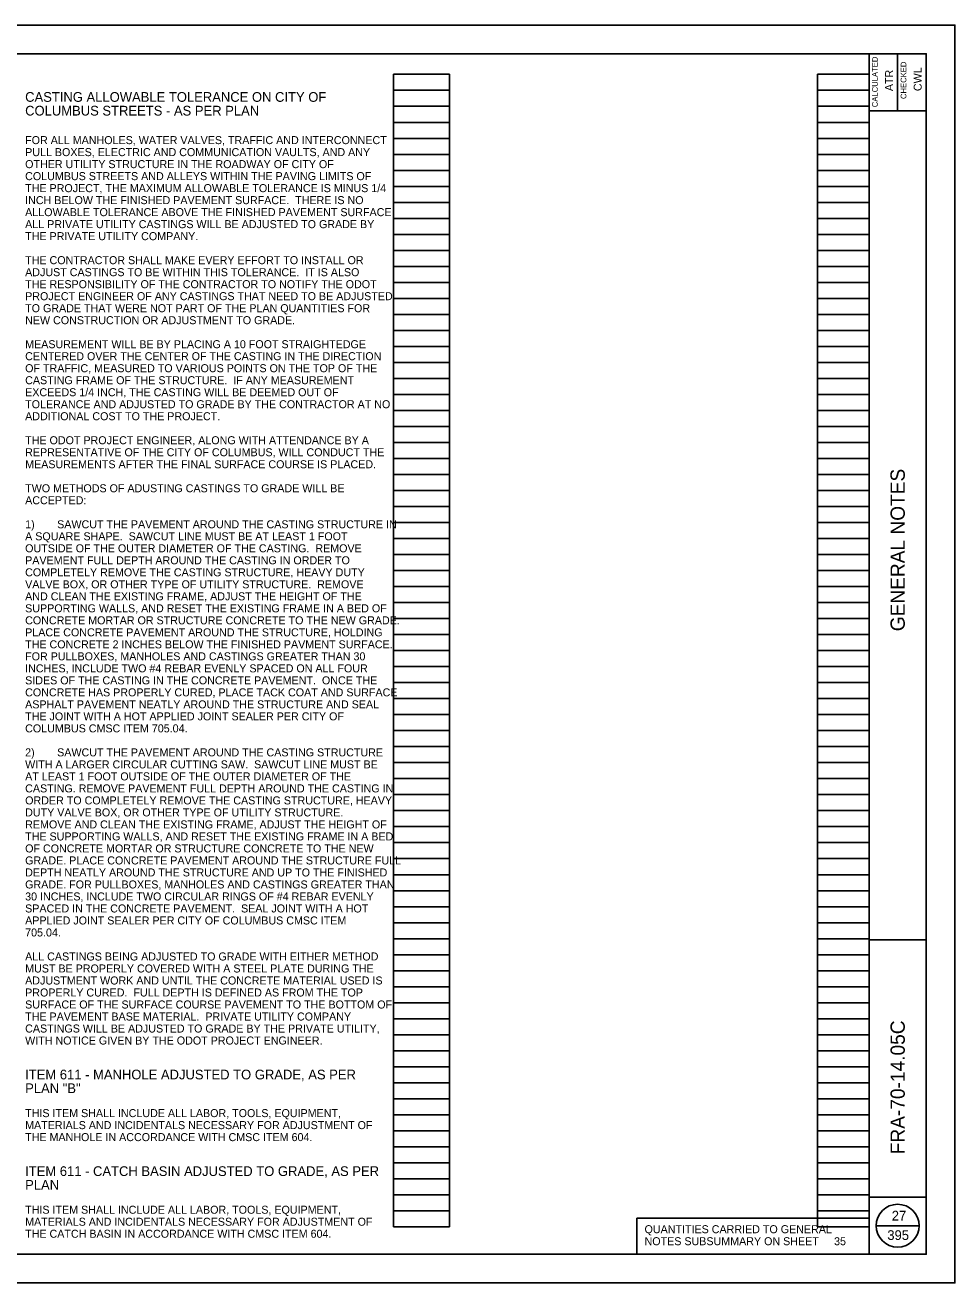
# Model space of a CAD drawing. Extents: x 0 to 34, y 0 to 22.
# Drawn here: x 17.74 to 34, y 0 to 22 of the extents above; entities that cross this region are included whole.
import ezdxf

# ---------------------------------------------------------------- set-up
doc = ezdxf.new("R2010")
doc.units = 0
for name, color, linetype in [('SC_Scratch1', 7, 'Continuous'), ('SH_Border', 7, 'Continuous'), ('SH_Cut_Line', 7, 'Continuous'), ('SH_Data', 7, 'Continuous'), ('SH_Text', 7, 'Continuous'), ('TX_P_1', 7, 'Continuous'), ('TX_P_Misc', 7, 'Continuous')]:
    doc.layers.add(name, color=color, linetype=linetype)

msp = doc.modelspace()

# ---------------------------------------------------------------- linework, layer by layer
at = {"layer": 'SC_Scratch1'}
for p, q in [((24.18, 0.98), (24.18, 21.14)), ((24.18, 21.14), (25.16, 21.14)), ((25.16, 0.98), (25.16, 21.14)), ((31.6, 0.98), (31.6, 21.14)), ((31.6, 21.14), (32.5, 21.14)), ((32.5, 0.98), (32.5, 21.14)), ((24.18, 20.86), (25.16, 20.86)), ((31.6, 20.86), (32.5, 20.86)), ((24.18, 20.58), (25.16, 20.58)), ((31.6, 20.58), (32.5, 20.58)), ((24.18, 20.3), (25.16, 20.3)), ((31.6, 20.3), (32.5, 20.3)), ((24.18, 20.02), (25.16, 20.02)), ((31.6, 20.02), (32.5, 20.02)), ((24.18, 19.74), (25.16, 19.74)), ((31.6, 19.74), (32.5, 19.74)), ((24.18, 19.46), (25.16, 19.46)), ((31.6, 19.46), (32.5, 19.46)), ((24.18, 19.18), (25.16, 19.18)), ((31.6, 19.18), (32.5, 19.18)), ((24.18, 18.9), (25.16, 18.9)), ((31.6, 18.9), (32.5, 18.9)), ((24.18, 18.62), (25.16, 18.62)), ((31.6, 18.62), (32.5, 18.62)), ((24.18, 18.34), (25.16, 18.34)), ((31.6, 18.34), (32.5, 18.34)), ((24.18, 18.06), (25.16, 18.06)), ((31.6, 18.06), (32.5, 18.06)), ((24.18, 17.78), (25.16, 17.78)), ((31.6, 17.78), (32.5, 17.78)), ((24.18, 17.5), (25.16, 17.5)), ((31.6, 17.5), (32.5, 17.5)), ((24.18, 17.22), (25.16, 17.22)), ((31.6, 17.22), (32.5, 17.22)), ((24.18, 16.94), (25.16, 16.94)), ((31.6, 16.94), (32.5, 16.94)), ((24.18, 16.66), (25.16, 16.66)), ((31.6, 16.66), (32.5, 16.66)), ((24.18, 16.38), (25.16, 16.38)), ((31.6, 16.38), (32.5, 16.38)), ((24.18, 16.1), (25.16, 16.1)), ((31.6, 16.1), (32.5, 16.1)), ((24.18, 15.82), (25.16, 15.82)), ((31.6, 15.82), (32.5, 15.82)), ((24.18, 15.54), (25.16, 15.54)), ((31.6, 15.54), (32.5, 15.54)), ((24.18, 15.26), (25.16, 15.26)), ((31.6, 15.26), (32.5, 15.26)), ((24.18, 14.98), (25.16, 14.98)), ((31.6, 14.98), (32.5, 14.98)), ((24.18, 14.7), (25.16, 14.7)), ((31.6, 14.7), (32.5, 14.7)), ((24.18, 14.42), (25.16, 14.42)), ((31.6, 14.42), (32.5, 14.42)), ((24.18, 14.14), (25.16, 14.14)), ((31.6, 14.14), (32.5, 14.14)), ((24.18, 13.86), (25.16, 13.86)), ((31.6, 13.86), (32.5, 13.86)), ((24.18, 13.58), (25.16, 13.58)), ((31.6, 13.58), (32.5, 13.58)), ((24.18, 13.3), (25.16, 13.3)), ((31.6, 13.3), (32.5, 13.3)), ((24.18, 13.02), (25.16, 13.02)), ((31.6, 13.02), (32.5, 13.02)), ((24.18, 12.74), (25.16, 12.74)), ((31.6, 12.74), (32.5, 12.74)), ((24.18, 12.46), (25.16, 12.46)), ((31.6, 12.46), (32.5, 12.46)), ((24.18, 12.18), (25.16, 12.18)), ((31.6, 12.18), (32.5, 12.18)), ((24.18, 11.9), (25.16, 11.9)), ((31.6, 11.9), (32.5, 11.9)), ((24.18, 11.62), (25.16, 11.62)), ((31.6, 11.62), (32.5, 11.62)), ((24.18, 11.34), (25.16, 11.34)), ((31.6, 11.34), (32.5, 11.34)), ((24.18, 11.06), (25.16, 11.06)), ((31.6, 11.06), (32.5, 11.06)), ((24.18, 10.78), (25.16, 10.78)), ((31.6, 10.78), (32.5, 10.78)), ((24.18, 10.5), (25.16, 10.5)), ((31.6, 10.5), (32.5, 10.5)), ((24.18, 10.22), (25.16, 10.22)), ((31.6, 10.22), (32.5, 10.22)), ((24.18, 9.94), (25.16, 9.94)), ((31.6, 9.94), (32.5, 9.94)), ((24.18, 9.66), (25.16, 9.66)), ((31.6, 9.66), (32.5, 9.66)), ((24.18, 9.38), (25.16, 9.38)), ((31.6, 9.38), (32.5, 9.38)), ((24.18, 9.1), (25.16, 9.1)), ((31.6, 9.1), (32.5, 9.1)), ((24.18, 8.82), (25.16, 8.82)), ((31.6, 8.82), (32.5, 8.82)), ((24.18, 8.54), (25.16, 8.54)), ((31.6, 8.54), (32.5, 8.54)), ((24.18, 8.26), (25.16, 8.26)), ((31.6, 8.26), (32.5, 8.26)), ((24.18, 7.98), (25.16, 7.98)), ((31.6, 7.98), (32.5, 7.98)), ((24.18, 7.7), (25.16, 7.7)), ((31.6, 7.7), (32.5, 7.7)), ((24.18, 7.42), (25.16, 7.42)), ((31.6, 7.42), (32.5, 7.42)), ((24.18, 7.14), (25.16, 7.14)), ((31.6, 7.14), (32.5, 7.14)), ((24.18, 6.86), (25.16, 6.86)), ((31.6, 6.86), (32.5, 6.86)), ((24.18, 6.58), (25.16, 6.58)), ((31.6, 6.58), (32.5, 6.58)), ((24.18, 6.3), (25.16, 6.3)), ((31.6, 6.3), (32.5, 6.3)), ((24.18, 6.02), (25.16, 6.02)), ((31.6, 6.02), (32.5, 6.02)), ((24.18, 5.74), (25.16, 5.74)), ((31.6, 5.74), (32.5, 5.74)), ((24.18, 5.46), (25.16, 5.46)), ((31.6, 5.46), (32.5, 5.46)), ((24.18, 5.18), (25.16, 5.18)), ((31.6, 5.18), (32.5, 5.18)), ((24.18, 4.9), (25.16, 4.9)), ((31.6, 4.9), (32.5, 4.9)), ((24.18, 4.62), (25.16, 4.62)), ((31.6, 4.62), (32.5, 4.62)), ((24.18, 4.34), (25.16, 4.34)), ((31.6, 4.34), (32.5, 4.34)), ((24.18, 4.06), (25.16, 4.06)), ((31.6, 4.06), (32.5, 4.06)), ((24.18, 3.78), (25.16, 3.78)), ((31.6, 3.78), (32.5, 3.78)), ((24.18, 3.5), (25.16, 3.5)), ((31.6, 3.5), (32.5, 3.5)), ((24.18, 3.22), (25.16, 3.22)), ((31.6, 3.22), (32.5, 3.22)), ((24.18, 2.94), (25.16, 2.94)), ((31.6, 2.94), (32.5, 2.94)), ((24.18, 2.66), (25.16, 2.66)), ((31.6, 2.66), (32.5, 2.66)), ((24.18, 2.38), (25.16, 2.38)), ((31.6, 2.38), (32.5, 2.38)), ((24.18, 2.1), (25.16, 2.1)), ((31.6, 2.1), (32.5, 2.1)), ((24.18, 1.82), (25.16, 1.82)), ((31.6, 1.82), (32.5, 1.82)), ((24.18, 1.54), (25.16, 1.54)), ((31.6, 1.54), (32.5, 1.54)), ((24.18, 1.26), (25.16, 1.26)), ((31.6, 1.26), (32.5, 1.26)), ((24.18, 0.98), (25.16, 0.98)), ((31.6, 0.98), (32.5, 0.98))]:
    msp.add_line(p, q, dxfattribs=at)
at = {"layer": 'SH_Border'}
for p, q in [((32.5, 0.5), (32.5, 21.5)), ((33, 21.5), (33, 20.5)), ((32.5, 20.5), (33.5, 20.5)), ((32.5, 6), (33.5, 6)), ((32.5, 1.5), (33.5, 1.5))]:
    msp.add_line(p, q, dxfattribs=at)
msp.add_lwpolyline([(2, 21.5), (33.5, 21.5), (33.5, 0.5), (2, 0.5)], close=True, dxfattribs=at)
at = {"layer": 'SH_Cut_Line'}
msp.add_lwpolyline([(0, 0), (34, 0), (34, 22), (0, 22)], close=True, dxfattribs=at)
at = {"layer": 'SH_Data'}
msp.add_line((32.625, 1), (33.375, 1), dxfattribs=at)
msp.add_circle((33, 1), 0.375, dxfattribs=at)
at = {"layer": 'TX_P_1'}
msp.add_lwpolyline([(28.437, 1.132), (32.5, 1.132), (32.5, 0.5), (28.437, 0.5)], close=True, dxfattribs=at)

# ---------------------------------------------------------------- texts
at = {"layer": 'SH_Data'}
for s, height, p in [('CALCULATED', 0.1, (32.652, 20.565)), ('CHECKED', 0.1, (33.152, 20.708)), ('ATR', 0.14, (32.92, 20.846)), ('CWL', 0.14, (33.42, 20.846)), ('GENERAL NOTES', 0.25, (33.125, 11.398)), ('FRA-70-14.05C', 0.25, (33.125, 2.249))]:
    msp.add_text(s, height=height, rotation=90, dxfattribs=at).set_placement(p)
for s, p in [('27', (32.897, 1.09)), ('395', (32.819, 0.75))]:
    msp.add_text(s, height=0.17, dxfattribs=at).set_placement(p)
at = {"layer": 'SH_Text'}
for s, p in [('FOR ALL MANHOLES, WATER VALVES, TRAFFIC AND INTERCONNECT ', (17.74, 19.919)), ('PULL BOXES, ELECTRIC AND COMMUNICATION VAULTS, AND ANY ', (17.74, 19.709)), ('OTHER UTILITY STRUCTURE IN THE ROADWAY OF CITY OF ', (17.74, 19.499)), ('COLUMBUS STREETS AND ALLEYS WITHIN THE PAVING LIMITS OF ', (17.74, 19.289)), ('THE PROJECT, THE MAXIMUM ALLOWABLE TOLERANCE IS MINUS 1/4 ', (17.74, 19.079)), ('INCH BELOW THE FINISHED PAVEMENT SURFACE.  THERE IS NO ', (17.74, 18.869)), ('ALLOWABLE TOLERANCE ABOVE THE FINISHED PAVEMENT SURFACE. ', (17.74, 18.659)), ('ALL PRIVATE UTILITY CASTINGS WILL BE ADJUSTED TO GRADE BY ', (17.74, 18.449)), ('THE PRIVATE UTILITY COMPANY.', (17.74, 18.239)), ('THE CONTRACTOR SHALL MAKE EVERY EFFORT TO INSTALL OR ', (17.74, 17.819)), ('ADJUST CASTINGS TO BE WITHIN THIS TOLERANCE.  IT IS ALSO ', (17.74, 17.609)), ('THE RESPONSIBILITY OF THE CONTRACTOR TO NOTIFY THE ODOT ', (17.74, 17.399)), ('PROJECT ENGINEER OF ANY CASTINGS THAT NEED TO BE ADJUSTED ', (17.74, 17.189)), ('TO GRADE THAT WERE NOT PART OF THE PLAN QUANTITIES FOR ', (17.74, 16.979)), ('NEW CONSTRUCTION OR ADJUSTMENT TO GRADE.', (17.74, 16.769)), ('CENTERED OVER THE CENTER OF THE CASTING IN THE DIRECTION ', (17.74, 16.139)), ('MEASUREMENT WILL BE BY PLACING A 10 FOOT STRAIGHTEDGE ', (17.74, 16.349)), ('OF TRAFFIC, MEASURED TO VARIOUS POINTS ON THE TOP OF THE ', (17.74, 15.929)), ('CASTING FRAME OF THE STRUCTURE.  IF ANY MEASUREMENT ', (17.74, 15.719)), ('EXCEEDS 1/4 INCH, THE CASTING WILL BE DEEMED OUT OF ', (17.74, 15.509)), ('TOLERANCE AND ADJUSTED TO GRADE BY THE CONTRACTOR AT NO ', (17.74, 15.299)), ('ADDITIONAL COST TO THE PROJECT.', (17.74, 15.089)), ('THE ODOT PROJECT ENGINEER, ALONG WITH ATTENDANCE BY A ', (17.74, 14.669)), ('REPRESENTATIVE OF THE CITY OF COLUMBUS, WILL CONDUCT THE ', (17.74, 14.459)), ('MEASUREMENTS AFTER THE FINAL SURFACE COURSE IS PLACED. ', (17.74, 14.249)), ('TWO METHODS OF ADUSTING CASTINGS TO GRADE WILL BE ', (17.74, 13.829)), ('ACCEPTED:', (17.74, 13.619)), ('1)', (17.74, 13.199)), ('SAWCUT THE PAVEMENT AROUND THE CASTING STRUCTURE IN ', (18.3, 13.199)), ('A SQUARE SHAPE.  SAWCUT LINE MUST BE AT LEAST 1 FOOT ', (17.74, 12.989)), ('OUTSIDE OF THE OUTER DIAMETER OF THE CASTING.  REMOVE ', (17.74, 12.779)), ('PAVEMENT FULL DEPTH AROUND THE CASTING IN ORDER TO ', (17.74, 12.569)), ('COMPLETELY REMOVE THE CASTING STRUCTURE, HEAVY DUTY ', (17.74, 12.359)), ('VALVE BOX, OR OTHER TYPE OF UTILITY STRUCTURE.  REMOVE ', (17.74, 12.149)), ('AND CLEAN THE EXISTING FRAME, ADJUST THE HEIGHT OF THE ', (17.74, 11.939)), ('SUPPORTING WALLS, AND RESET THE EXISTING FRAME IN A BED OF ', (17.74, 11.729)), ('CONCRETE MORTAR OR STRUCTURE CONCRETE TO THE NEW GRADE. ', (17.74, 11.519)), ('PLACE CONCRETE PAVEMENT AROUND THE STRUCTURE, HOLDING ', (17.74, 11.309)), ('THE CONCRETE 2 INCHES BELOW THE FINISHED PAVMENT SURFACE.  ', (17.74, 11.099)), ('FOR PULLBOXES, MANHOLES AND CASTINGS GREATER THAN 30 ', (17.74, 10.889)), ('INCHES, INCLUDE TWO #4 REBAR EVENLY SPACED ON ALL FOUR ', (17.74, 10.679)), ('SIDES OF THE CASTING IN THE CONCRETE PAVEMENT.  ONCE THE ', (17.74, 10.469)), ('CONCRETE HAS PROPERLY CURED, PLACE TACK COAT AND SURFACE ', (17.74, 10.259)), ('ASPHALT PAVEMENT NEATLY AROUND THE STRUCTURE AND SEAL ', (17.74, 10.049)), ('THE JOINT WITH A HOT APPLIED JOINT SEALER PER CITY OF ', (17.74, 9.839)), ('COLUMBUS CMSC ITEM 705.04.', (17.74, 9.629)), ('2)', (17.74, 9.209)), ('SAWCUT THE PAVEMENT AROUND THE CASTING STRUCTURE ', (18.3, 9.209)), ('WITH A LARGER CIRCULAR CUTTING SAW.  SAWCUT LINE MUST BE ', (17.74, 8.999)), ('AT LEAST 1 FOOT OUTSIDE OF THE OUTER DIAMETER OF THE ', (17.74, 8.789)), ('CASTING. REMOVE PAVEMENT FULL DEPTH AROUND THE CASTING IN ', (17.74, 8.579)), ('ORDER TO COMPLETELY REMOVE THE CASTING STRUCTURE, HEAVY ', (17.74, 8.369)), ('DUTY VALVE BOX, OR OTHER TYPE OF UTILITY STRUCTURE.  ', (17.74, 8.159)), ('REMOVE AND CLEAN THE EXISTING FRAME, ADJUST THE HEIGHT OF ', (17.74, 7.949)), ('THE SUPPORTING WALLS, AND RESET THE EXISTING FRAME IN A BED ', (17.74, 7.739)), ('OF CONCRETE MORTAR OR STRUCTURE CONCRETE TO THE NEW ', (17.74, 7.529)), ('GRADE. PLACE CONCRETE PAVEMENT AROUND THE STRUCTURE FULL ', (17.74, 7.319)), ('GRADE. FOR PULLBOXES, MANHOLES AND CASTINGS GREATER THAN ', (17.74, 6.899)), ('DEPTH NEATLY AROUND THE STRUCTURE AND UP TO THE FINISHED ', (17.74, 7.109)), ('30 INCHES, INCLUDE TWO CIRCULAR RINGS OF #4 REBAR EVENLY ', (17.74, 6.689)), ('SPACED IN THE CONCRETE PAVEMENT.  SEAL JOINT WITH A HOT ', (17.74, 6.479)), ('APPLIED JOINT SEALER PER CITY OF COLUMBUS CMSC ITEM ', (17.74, 6.269)), ('705.04.', (17.74, 6.059)), ('ALL CASTINGS BEING ADJUSTED TO GRADE WITH EITHER METHOD ', (17.74, 5.639)), ('MUST BE PROPERLY COVERED WITH A STEEL PLATE DURING THE ', (17.74, 5.429)), ('ADJUSTMENT WORK AND UNTIL THE CONCRETE MATERIAL USED IS ', (17.74, 5.219)), ('PROPERLY CURED.  FULL DEPTH IS DEFINED AS FROM THE TOP ', (17.74, 5.009)), ('SURFACE OF THE SURFACE COURSE PAVEMENT TO THE BOTTOM OF ', (17.74, 4.799)), ('THE PAVEMENT BASE MATERIAL.  PRIVATE UTILITY COMPANY ', (17.74, 4.589)), ('CASTINGS WILL BE ADJUSTED TO GRADE BY THE PRIVATE UTILITY, ', (17.74, 4.379)), ('WITH NOTICE GIVEN BY THE ODOT PROJECT ENGINEER.', (17.74, 4.169)), ('THIS ITEM SHALL INCLUDE ALL LABOR, TOOLS, EQUIPMENT, ', (17.74, 2.899)), ('MATERIALS AND INCIDENTALS NECESSARY FOR ADJUSTMENT OF ', (17.74, 2.689)), ('THE MANHOLE IN ACCORDANCE WITH CMSC ITEM 604.', (17.74, 2.479)), ('THIS ITEM SHALL INCLUDE ALL LABOR, TOOLS, EQUIPMENT, ', (17.74, 1.209)), ('MATERIALS AND INCIDENTALS NECESSARY FOR ADJUSTMENT OF ', (17.74, 0.999)), ('THE CATCH BASIN IN ACCORDANCE WITH CMSC ITEM 604.', (17.74, 0.789))]:
    msp.add_text(s, height=0.14, dxfattribs=at).set_placement(p)
at = {"layer": 'TX_P_1'}
for s, p in [('QUANTITIES CARRIED TO GENERAL', (28.573, 0.868)), ('NOTES SUBSUMMARY ON SHEET', (28.573, 0.658)), ('35', (31.888, 0.658))]:
    msp.add_text(s, height=0.14, dxfattribs=at).set_placement(p)
at = {"layer": 'TX_P_Misc'}
for s, p in [('CASTING ALLOWABLE TOLERANCE ON CITY OF ', (17.74, 20.659)), ('COLUMBUS STREETS - AS PER PLAN', (17.74, 20.419)), ('ITEM 611 - MANHOLE ADJUSTED TO GRADE, AS PER ', (17.74, 3.559)), ('PLAN "B"', (17.74, 3.319)), ('ITEM 611 - CATCH BASIN ADJUSTED TO GRADE, AS PER ', (17.74, 1.869)), ('PLAN', (17.74, 1.629))]:
    msp.add_text(s, height=0.17, dxfattribs=at).set_placement(p)

doc.saveas('drawing.dxf')
